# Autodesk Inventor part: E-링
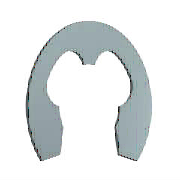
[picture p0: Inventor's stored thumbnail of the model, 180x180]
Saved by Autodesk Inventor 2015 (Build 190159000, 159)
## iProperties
IsCustomPart: 1
Created: 2012-02
Part Number: E-링
Material: 강철, 연강
Description: 일반용 테이퍼 및 줄어든 횡단면 리테이닝 링 - E-링 외부 시리즈 3CM1 리테이닝 링
Document SubType Name: Modeling
Standard: ANSI B27.7
Designer: mduedu
Standard Revision: 1999
Standards Organization: ANSI
Language: ko-KR
Size Designation: 6
Categories: <MemberInstance><Categories><Category DisplayName="샤프트 부품" InternalName="7f7aeb1f-a693-4053-b835-cee3144e0d98" Mnemonic="SHFT"><Category DisplayName="써클립" Inter
Density: 7.85 g/cm^3
Appearance: 파란색 - 벽 페인트 - 광택
Mass: 0.225854 g
Surface Area: 1.26477 cm^2
Volume: 0.0287712 cm^3
Author: mduedu
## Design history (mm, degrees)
sketch "스케치1"
  geometry: L1 (-0.485, 0.024)-(0, 0.024) reference; L2 (-3.206, 0)-(3.486, 0) reference; L3 (-2.223, -3.946)-(2.223, -3.946); L4 (0, 1.949)-(0, -3.479) reference; L5 (-2.91, -2.006)-(-2.435, -2.006); L6 (-0.485, -0.066)-(-0.485, 0.405); L7 (0, 2.574)-(2.53, 2.574); L8 (-2.223, -3.946)-(-3.022, -6.291); L9 (0, -0.551)-(-1.278, -0.551); L10 (2.223, -3.946)-(3.022, -6.291); L11 (2.91, -2.006)-(2.435, -2.006); L12 (0.485, -0.066)-(0.485, 0.405); C1 r 3 at (0, -2.976); A1 r 2.425 centre (0, -2.976) between (-2.297, -2.199) and (-2.223, -3.946); A2 r 0.485 centre (0, -0.066) between (-0.485, -0.066) and (0.485, -0.066); A3 r 5.55 centre (0, -2.976) between (4.27, -6.521) and (-4.27, -6.521); A4 r 3.88 centre (0, -2.976) between (-0.97, 0.78) and (-3.424, -1.15); A5 r 0.388 centre (-0.873, 0.405) between (-0.485, 0.405) and (-0.97, 0.78); A6 r 0.582 centre (-2.91, -1.424) between (-3.424, -1.15) and (-2.91, -2.006); A7 r 0.145 centre (-2.435, -2.152) between (-2.297, -2.199) and (-2.435, -2.006); A8 r 0.727 centre (-3.711, -6.057) between (-4.27, -6.521) and (-3.022, -6.291); A9 r 0.727 centre (3.711, -6.057) between (3.022, -6.291) and (4.27, -6.521); A10 r 2.425 centre (0, -2.976) between (2.223, -3.946) and (2.297, -2.199); A11 r 0.145 centre (2.435, -2.152) between (2.435, -2.006) and (2.297, -2.199); A12 r 0.582 centre (2.91, -1.424) between (2.91, -2.006) and (3.424, -1.15); A13 r 3.88 centre (0, -2.976) between (3.424, -1.15) and (0.97, 0.78); A14 r 0.388 centre (0.873, 0.405) between (0.97, 0.78) and (0.485, 0.405); 1 further point
  constraints: 30 point on circle, 20 end point, 15 centre point, 13 symmetric about line, 12 tangent, 8 point on line, 4 parallel, 2 coincident, 2 horizontal, 1 concentric, 1 perpendicular, 1 vertical alignment, 9 other
  dimensions: "d0" = 6 diameter of C1 (= WD); "d3" = 0.97 distance from line of A1.centre L3 (= 0.2 x ND); "d4" = 0.485 radius of A2 (= 0.1 x ND); "d5" = 11.1 diameter of A3 (= SD2); "d8" = 3.88 radius of A4 (= 0.8 x ND); "d9" = 0.97 distance from line of A1.centre L5 (= 0.2 x ND); "d10" = 0.388 radius of A5 (= 0.08 x ND); "d11" = 0.582 radius of A6 (= 0.12 x ND); "d12" = 0.1455 radius of A7 (= 0.03 x ND); "d13" = 0.7275 radius of A8 (= 0.15 x ND); "d14" = 2.425 distance from line of A1.centre L9 (= 0.5 x ND); "d15" = 2.425 radius of A1 (= 0.5 x ND)
extrude "본체" new body sketch "스케치1" distance "d16" = 0.6 (= SD); taper "d17" = 0 deg
workaxis "Work Axis1"
workaxis "Work Axis2"
workplane "Work Plane1"
body "Solid1"
other parameters: "ND" = 4.85 [user parameter; used in 14 equation terms], "SD" = 0.6 [user parameter; used in 1 equation term], "WD" = 6 (= WDMIN) [user parameter; used in 1 equation term], "d1" = 7.76 (= 1.6 x ND), "d2" = 4.85 (= ND), "SD2" = 11.1 [user parameter; used in 1 equation term], "d6" = 4.85 (= ND), "d7" = 0.7275 (= 0.15 x ND), "d18" = 0, "d19" = 0, "d27" = 0, "d28" = 0, "WDMIN" = 6 [user parameter; used in 1 equation term], "SNB" = 0.7 [user parameter], "WDMAX" = 7 [user parameter], "BUBRMI" = 1.2 [user parameter]
